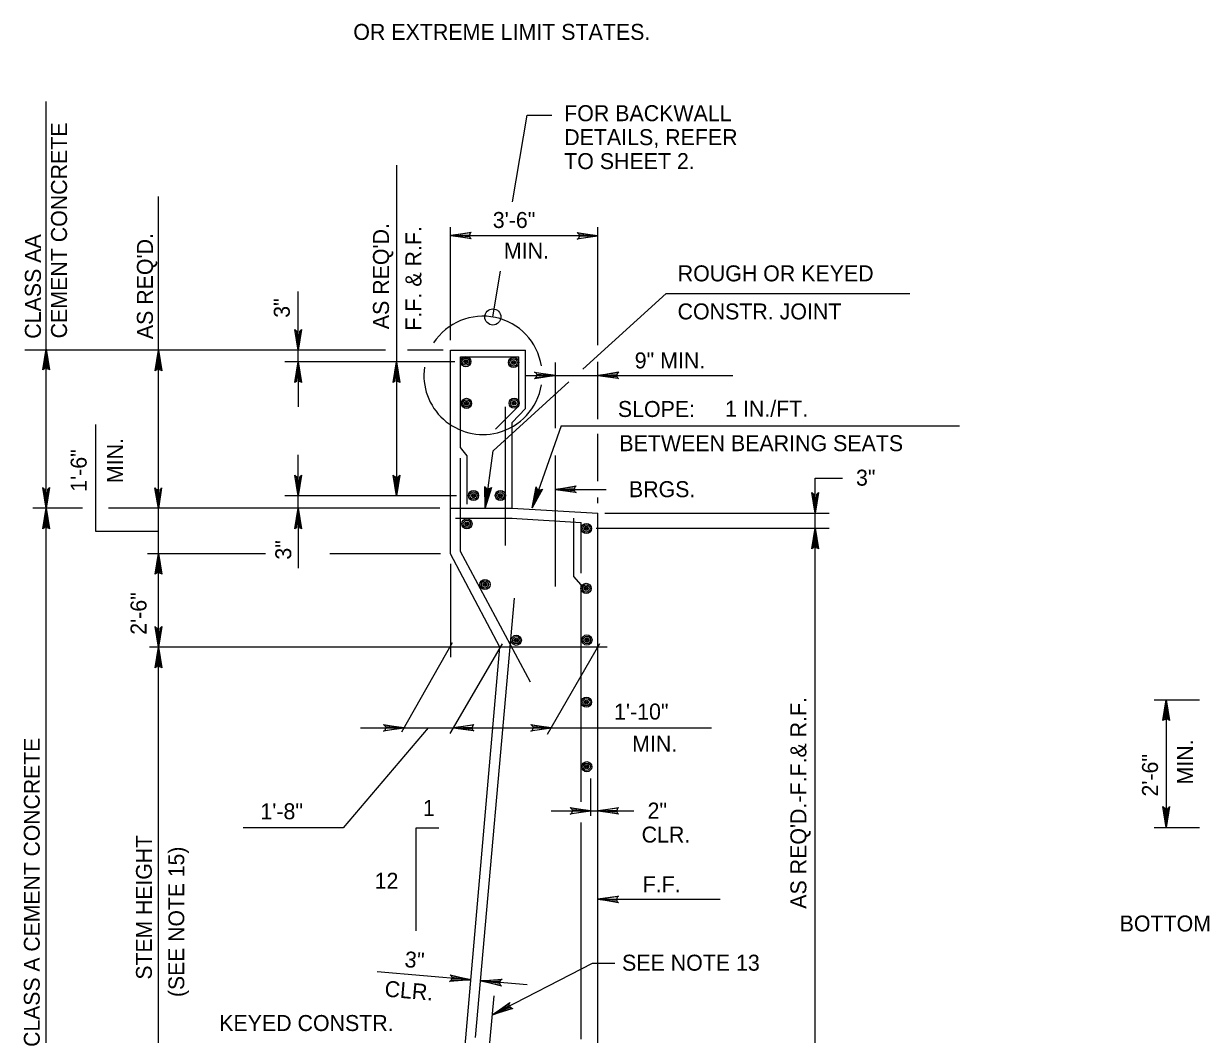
# Model space of a CAD drawing. Extents: x 235 to 2276, y 116 to 1308.
# Drawn here: x 855.9 to 1078.3, y 817.2 to 1006.9 of the extents above; entities that cross this region are included whole.
import ezdxf

# ---------------------------------------------------------------- set-up
doc = ezdxf.new("R2010")
doc.units = 0
doc.layers.add('1', color=7, linetype='Continuous')

msp = doc.modelspace()

# ---------------------------------------------------------------- linework, layer by layer
at = {"layer": '1'}
for p, q in [((860.12, 942.99), (860.12, 992.35)), ((947.67, 973.49), (950.43, 989.79)), ((950.43, 989.79), (955.07, 989.79)), ((925.92, 980.39), (925.92, 952.99)), ((881.22, 951.59), (881.22, 974.52)), ((936.06, 951.59), (936.06, 968.74)), ((963.72, 951.59), (963.72, 968.74)), ((936.06, 967.15), (963.72, 967.15)), ((944, 951.87), (945.46, 960.45)), ((907.47, 943.46), (907.47, 956.67)), ((960.91, 942.08), (976.53, 956.27)), ((976.53, 956.27), (1022.28, 956.27)), ((925.92, 952.99), (925.92, 941.43)), ((881.22, 945.65), (881.22, 951.59)), ((936.06, 947.52), (936.06, 951.59)), ((963.72, 946.59), (963.72, 951.59)), ((923.83, 945.65), (856.12, 945.65)), ((860.12, 915.96), (860.12, 945.65)), ((881.22, 915.96), (881.22, 945.65)), ((934.65, 945.65), (927.97, 945.65)), ((936.06, 907.37), (936.06, 945.65)), ((936.06, 945.65), (950.12, 945.65)), ((950.12, 934.71), (950.12, 945.65)), ((936.84, 943.46), (904.97, 943.46)), ((907.47, 943.46), (907.47, 935.02)), ((925.92, 943.46), (925.92, 918.3)), ((937.94, 944.4), (948.87, 944.4)), ((937.94, 927.37), (937.94, 944.4)), ((948.87, 935.18), (948.87, 944.4)), ((955.75, 930.99), (955.75, 943.34)), ((963.72, 941.43), (963.72, 943.46)), ((950.23, 940.91), (989.04, 940.91)), ((963.72, 932.65), (963.72, 941.43)), ((944.03, 926.74), (958.29, 939.7)), ((948.87, 935.18), (944.5, 930.8)), ((946.37, 908.93), (946.37, 935.02)), ((950.12, 934.71), (947.62, 932.05)), ((947.62, 915.96), (947.62, 932.05)), ((869.44, 911.59), (869.44, 931.69)), ((956.85, 931.43), (1031.62, 931.43)), ((963.72, 921.05), (963.72, 929.93)), ((907.47, 915.96), (907.47, 926.01)), ((939.19, 925.8), (937.94, 927.37)), ((937.94, 907.84), (937.94, 925.34)), ((939.19, 916.74), (939.19, 925.8)), ((942.62, 916.12), (944.03, 926.74)), ((955.75, 901.27), (955.75, 925.83)), ((1004.5, 912.21), (1004.5, 921.57)), ((1004.5, 921.57), (1009.63, 921.57)), ((955.75, 919.49), (965.28, 919.49)), ((937.15, 918.3), (904.97, 918.3)), ((963.72, 916.9), (963.72, 917.96)), ((866.93, 915.96), (857.62, 915.96)), ((860.12, 776.74), (860.12, 915.96)), ((934.03, 915.96), (871.82, 915.96)), ((881.22, 907.37), (881.22, 915.96)), ((907.47, 915.96), (907.47, 904.72)), ((936.06, 915.96), (947.62, 915.96)), ((947.62, 915.96), (963.72, 915.02)), ((963.72, 797.99), (963.72, 915.02)), ((965.01, 915.02), (1007.15, 915.02)), ((937, 914.09), (947.62, 914.09)), ((947.47, 914.09), (960.59, 913.3)), ((959.19, 903.15), (959.19, 914.09)), ((960.59, 903.77), (960.59, 913.3)), ((963.4, 912.21), (1007.15, 912.21)), ((1004.5, 800.65), (1004.5, 912.21)), ((881.22, 911.59), (869.44, 911.59)), ((951.06, 883.3), (937.94, 907.84)), ((901.29, 907.37), (879.17, 907.37)), ((881.22, 797.99), (881.22, 907.37)), ((934.19, 907.37), (913.4, 907.37)), ((945.28, 889.87), (936.06, 907.37)), ((936.06, 905.49), (936.06, 887.99)), ((960.59, 901.59), (959.19, 903.15)), ((960.59, 860.81), (960.59, 901.59)), ((940.75, 816.59), (948.09, 899.09)), ((965.44, 889.87), (879.5, 889.87)), ((936.37, 890.65), (926.84, 873.93)), ((945.75, 890.49), (935.9, 873.62)), ((937.31, 797.99), (945.28, 889.87)), ((964.03, 890.49), (954.19, 873.46)), ((1068.18, 879.97), (1076.68, 879.97)), ((1070.43, 879.97), (1070.43, 855.97)), ((931.84, 874.71), (915.9, 855.96)), ((919.12, 874.71), (936.53, 874.71)), ((936.53, 874.71), (954.97, 874.71)), ((954.97, 874.71), (985.06, 874.71)), ((962.39, 858.16), (962.39, 865.22)), ((954.97, 859.12), (962.39, 859.12)), ((962.39, 859.12), (963.72, 859.12)), ((963.72, 859.12), (970.49, 859.12)), ((960.59, 816.24), (960.59, 856.93)), ((915.9, 855.96), (897.12, 855.96)), ((929.61, 855.96), (933.83, 855.96)), ((929.61, 836.59), (929.61, 855.96)), ((1068.18, 855.97), (1076.68, 855.97)), ((963.72, 842.52), (986.69, 842.52)), ((962.66, 830.44), (943.9, 820.8)), ((966.9, 830.44), (962.66, 830.44)), ((939.65, 827.37), (922.25, 828.9)), ((950.44, 826.43), (941.69, 827.21)), ((941.1, 789.33), (944.23, 824.4))]:
    msp.add_line(p, q, dxfattribs=at)
for points in [[(939.78, 966.65), (939.66, 966.9), (936.03, 967.15), (939.78, 966.65), (939.91, 966.53), (936.03, 967.15), (939.66, 967.28), (939.78, 967.65), (936.03, 967.15), (939.91, 967.78), (939.78, 967.65)], [(959.94, 967.63), (960.19, 967.38), (963.69, 967.13), (959.94, 967.63), (959.81, 967.75), (963.69, 967.13), (960.19, 967), (960.06, 966.63), (963.69, 967.13), (959.81, 966.5), (960.06, 966.63)], [(907.97, 949.4), (907.72, 949.15), (907.47, 945.65), (907.97, 949.4), (908.09, 949.52), (907.47, 945.65), (907.34, 949.15), (907.09, 949.27), (907.47, 945.65), (906.84, 949.52), (907.09, 949.27)], [(859.61, 942.09), (859.86, 942.22), (860.11, 945.84), (859.61, 942.09), (859.48, 941.97), (860.11, 945.84), (860.23, 942.22), (860.61, 942.09), (860.11, 945.84), (860.73, 941.97), (860.61, 942.09)], [(880.71, 941.9), (880.96, 942.03), (881.21, 945.65), (880.71, 941.9), (880.59, 941.78), (881.21, 945.65), (881.34, 942.03), (881.71, 941.9), (881.21, 945.65), (881.84, 941.78), (881.71, 941.9)], [(906.97, 939.71), (907.22, 939.84), (907.47, 943.46), (906.97, 939.71), (906.84, 939.59), (907.47, 943.46), (907.59, 939.84), (907.97, 939.71), (907.47, 943.46), (908.09, 939.59), (907.97, 939.71)], [(925.42, 939.71), (925.67, 939.84), (925.92, 943.46), (925.42, 939.71), (925.29, 939.59), (925.92, 943.46), (926.04, 939.84), (926.42, 939.71), (925.92, 943.46), (926.54, 939.59), (926.42, 939.71)], [(952.09, 941.4), (952.21, 941.15), (955.84, 940.9), (952.09, 941.4), (951.84, 941.52), (955.84, 940.9), (952.21, 940.77), (952.09, 940.52), (955.84, 940.9), (951.84, 940.27), (952.09, 940.52)], [(967.47, 940.41), (967.34, 940.66), (963.72, 940.91), (967.47, 940.41), (967.59, 940.29), (963.72, 940.91), (967.34, 941.04), (967.47, 941.41), (963.72, 940.91), (967.59, 941.54), (967.47, 941.41)], [(956.85, 931.43), (951.37, 915.96)], [(907.97, 922.05), (907.72, 921.8), (907.47, 918.3), (907.97, 922.05), (908.09, 922.18), (907.47, 918.3), (907.34, 921.8), (907.09, 921.93), (907.47, 918.3), (906.84, 922.18), (907.09, 921.93)], [(926.42, 922.05), (926.17, 921.8), (925.92, 918.3), (926.42, 922.05), (926.54, 922.18), (925.92, 918.3), (925.79, 921.8), (925.54, 921.93), (925.92, 918.3), (925.29, 922.18), (925.54, 921.93)], [(860.62, 919.72), (860.37, 919.47), (860.12, 915.97), (860.62, 919.72), (860.75, 919.84), (860.12, 915.97), (860, 919.47), (859.62, 919.59), (860.12, 915.97), (859.5, 919.84), (859.62, 919.59)], [(881.69, 919.65), (881.44, 919.4), (881.19, 915.9), (881.69, 919.65), (881.81, 919.77), (881.19, 915.9), (881.06, 919.4), (880.69, 919.52), (881.19, 915.9), (880.56, 919.77), (880.69, 919.52)], [(943.53, 919.7), (943.24, 919.6), (942.56, 916.02), (943.53, 919.7), (943.72, 919.87), (942.56, 916.02), (942.86, 919.64), (942.61, 919.81), (942.56, 916.02), (942.46, 920.04), (942.61, 919.81)], [(953.09, 919.41), (952.78, 919.37), (951.38, 916.01), (953.09, 919.41), (953.31, 919.54), (951.38, 916.01), (952.42, 919.5), (952.21, 919.71), (951.38, 916.01), (952.11, 919.96), (952.21, 919.71)], [(959.48, 919), (959.36, 919.25), (955.73, 919.5), (959.48, 919), (959.61, 918.88), (955.73, 919.5), (959.36, 919.63), (959.48, 920), (955.73, 919.5), (959.61, 920.13), (959.48, 920)], [(1005, 918.77), (1004.75, 918.52), (1004.5, 915.02), (1005, 918.77), (1005.12, 918.9), (1004.5, 915.02), (1004.37, 918.52), (1004.12, 918.65), (1004.5, 915.02), (1003.87, 918.9), (1004.12, 918.65)], [(859.62, 912.23), (859.87, 912.35), (860.12, 915.98), (859.62, 912.23), (859.5, 912.1), (860.12, 915.98), (860.25, 912.35), (860.62, 912.23), (860.12, 915.98), (860.75, 912.1), (860.62, 912.23)], [(906.97, 912.21), (907.22, 912.34), (907.47, 915.96), (906.97, 912.21), (906.84, 912.09), (907.47, 915.96), (907.59, 912.34), (907.97, 912.21), (907.47, 915.96), (908.09, 912.09), (907.97, 912.21)], [(1004.04, 908.46), (1004.29, 908.59), (1004.54, 912.21), (1004.04, 908.46), (1003.91, 908.34), (1004.54, 912.21), (1004.66, 908.59), (1005.04, 908.46), (1004.54, 912.21), (1005.16, 908.34), (1005.04, 908.46)], [(880.73, 903.7), (880.98, 903.82), (881.23, 907.45), (880.73, 903.7), (880.61, 903.57), (881.23, 907.45), (881.36, 903.82), (881.73, 903.7), (881.23, 907.45), (881.86, 903.57), (881.73, 903.7)], [(881.7, 893.62), (881.45, 893.37), (881.2, 889.87), (881.7, 893.62), (881.83, 893.75), (881.2, 889.87), (881.08, 893.37), (880.7, 893.5), (881.2, 889.87), (880.58, 893.75), (880.7, 893.5)], [(880.72, 886.12), (880.97, 886.24), (881.22, 889.87), (880.72, 886.12), (880.59, 885.99), (881.22, 889.87), (881.34, 886.24), (881.72, 886.12), (881.22, 889.87), (881.84, 885.99), (881.72, 886.12)], [(1069.93, 876.22), (1070.3, 876.34), (1070.43, 879.97), (1069.93, 876.22), (1069.8, 876.09), (1070.43, 879.97), (1070.68, 876.34), (1070.93, 876.22), (1070.43, 879.97), (1071.05, 876.09), (1070.93, 876.22)], [(923.56, 875.21), (923.81, 874.96), (927.31, 874.71), (923.56, 875.21), (923.44, 875.34), (927.31, 874.71), (923.81, 874.59), (923.69, 874.21), (927.31, 874.71), (923.44, 874.09), (923.69, 874.21)], [(940.28, 874.24), (940.15, 874.49), (936.53, 874.74), (940.28, 874.24), (940.4, 874.12), (936.53, 874.74), (940.15, 874.87), (940.28, 875.24), (936.53, 874.74), (940.4, 875.37), (940.28, 875.24)], [(951.23, 875.21), (951.48, 874.96), (954.98, 874.71), (951.23, 875.21), (951.11, 875.34), (954.98, 874.71), (951.48, 874.59), (951.36, 874.21), (954.98, 874.71), (951.11, 874.09), (951.36, 874.21)], [(958.64, 859.62), (958.89, 859.37), (962.39, 859.12), (958.64, 859.62), (958.52, 859.75), (962.39, 859.12), (958.89, 859), (958.77, 858.62), (962.39, 859.12), (958.52, 858.5), (958.77, 858.62)], [(967.47, 858.62), (967.34, 858.87), (963.72, 859.12), (967.47, 858.62), (967.59, 858.5), (963.72, 859.12), (967.34, 859.25), (967.47, 859.62), (963.72, 859.12), (967.59, 859.75), (967.47, 859.62)], [(1070.93, 859.72), (1070.68, 859.59), (1070.43, 855.97), (1070.93, 859.72), (1071.05, 859.97), (1070.43, 855.97), (1070.3, 859.59), (1070.05, 859.72), (1070.43, 855.97), (1069.8, 859.97), (1070.05, 859.72)], [(967.43, 842.01), (967.31, 842.26), (963.68, 842.51), (967.43, 842.01), (967.56, 841.88), (963.68, 842.51), (967.31, 842.63), (967.43, 843.01), (963.68, 842.51), (967.56, 843.13), (967.43, 843.01)], [(936.17, 828.17), (936.29, 827.89), (939.9, 827.37), (936.17, 828.17), (935.99, 828.35), (939.9, 827.37), (936.26, 827.51), (936.1, 827.25), (939.9, 827.37), (935.88, 827.09), (936.1, 827.25)], [(945.44, 826.41), (945.32, 826.69), (941.72, 827.22), (945.44, 826.41), (945.62, 826.22), (941.72, 827.22), (945.35, 827.07), (945.51, 827.33), (941.72, 827.22), (945.73, 827.49), (945.51, 827.33)], [(947.49, 822.08), (947.24, 822.27), (943.9, 820.8), (947.49, 822.08), (947.74, 822.02), (943.9, 820.8), (947.07, 822.6), (947.06, 822.91), (943.9, 820.8), (947.17, 823.16), (947.06, 822.91)]]:
    msp.add_lwpolyline(points, dxfattribs=at)
for centre, radius in [((944, 951.87), 1.51), ((938.93, 943.48), 0.954), ((938.93, 943.48), 0.681), ((938.93, 943.48), 0.372), ((938.93, 943.48), 0.188), ((938.93, 943.48), 0.0805), ((947.89, 943.32), 0.954), ((947.89, 943.32), 0.681), ((947.89, 943.32), 0.372), ((947.89, 943.32), 0.188), ((947.89, 943.32), 0.0805), ((939.04, 935.65), 0.954), ((947.99, 935.69), 0.954), ((939.04, 935.65), 0.681), ((939.04, 935.65), 0.372), ((939.04, 935.65), 0.188), ((939.04, 935.65), 0.0805), ((947.99, 935.69), 0.681), ((947.99, 935.69), 0.372), ((947.99, 935.69), 0.188), ((947.99, 935.69), 0.0805), ((940.37, 918.33), 0.954), ((940.37, 918.33), 0.681), ((940.37, 918.33), 0.372), ((945.41, 918.33), 0.954), ((945.41, 918.33), 0.681), ((945.41, 918.33), 0.372), ((940.37, 918.33), 0.188), ((940.37, 918.33), 0.0805), ((945.41, 918.33), 0.188), ((945.41, 918.33), 0.0805), ((939.13, 913.01), 0.954), ((939.13, 913.01), 0.681), ((939.13, 913.01), 0.372), ((939.13, 913.01), 0.188), ((939.13, 913.01), 0.0805), ((961.56, 912.15), 0.954), ((961.56, 912.15), 0.681), ((961.56, 912.15), 0.372), ((961.56, 912.15), 0.188), ((961.56, 912.15), 0.0805), ((942.52, 901.64), 0.954), ((942.52, 901.64), 0.681), ((942.52, 901.64), 0.372), ((942.52, 901.64), 0.188), ((942.52, 901.64), 0.0805), ((961.5, 900.9), 0.954), ((961.5, 900.9), 0.681), ((961.5, 900.9), 0.372), ((961.5, 900.9), 0.188), ((961.5, 900.9), 0.0805), ((948.4, 891.16), 0.954), ((961.66, 891.21), 0.954), ((948.4, 891.16), 0.681), ((948.4, 891.16), 0.372), ((948.4, 891.16), 0.188), ((948.4, 891.16), 0.0805), ((961.66, 891.21), 0.681), ((961.66, 891.21), 0.372), ((961.66, 891.21), 0.188), ((961.66, 891.21), 0.0805), ((961.56, 879.53), 0.954), ((961.56, 879.53), 0.681), ((961.56, 879.53), 0.372), ((961.56, 879.53), 0.188), ((961.56, 879.53), 0.0805), ((961.62, 867.41), 0.954), ((961.62, 867.41), 0.681), ((961.62, 867.41), 0.372), ((961.62, 867.41), 0.188), ((961.62, 867.41), 0.0805)]:
    msp.add_circle(centre, radius, dxfattribs=at)
for start, end in [(9.2933, 146.6735), (172.0304, 284.0362), (284.0362, 350.7067)]:
    msp.add_arc((942.15, 940.91), 11.11, start, end, dxfattribs=at)

# ---------------------------------------------------------------- texts
for s, height, p in [('    OR EXTREME LIMIT STATES.', 3.003, (913.33, 1003.9)), ('FOR BACKWALL', 3, (957.39, 988.64)), ('DETAILS, REFER', 3, (957.39, 984.14)), ('TO SHEET 2.', 3, (957.39, 979.64)), ('3\'-6"', 3.003, (943.98, 968.58)), ('MIN.', 3, (946.07, 962.85)), ('ROUGH OR KEYED', 3, (978.71, 958.56)), ('CONSTR. JOINT', 3, (978.68, 951.41)), ('9" MIN.', 3.003, (970.63, 942.21)), ('SLOPE:', 3, (967.47, 933.09)), ('1 IN./FT.', 3.003, (987.6, 933.15)), ('BETWEEN BEARING SEATS', 3, (967.75, 926.67)), ('3"', 3.003, (1012.18, 920.19)), ('  BRGS.', 3, (967.31, 918.03)), ('1\'-10"', 3.003, (966.75, 876.26)), ('MIN.', 3, (970.14, 870.23)), ('1 ', 3, (930.86, 858.17)), ('1\'-8"', 3.003, (900.35, 857.54)), (' 2"', 3, (971.93, 857.67)), ('CLR.', 3, (971.93, 853.17)), ('12', 3, (921.8, 844.49)), ('F.F.', 3, (972.13, 843.83)), ('BOTTOM REBAR MAT (TYP.)', 3, (1061.68, 836.47)), ('SEE NOTE 13', 3, (968.25, 829.11)), ('KEYED CONSTR.', 3, (892.61, 817.78))]:
    msp.add_text(s, height=height, dxfattribs=at).set_placement(p)
for s, height, rotation, p in [('CEMENT CONCRETE', 3, 90, (864.04, 947.85)), ("AS REQ'D.", 3, 90, (924.49, 949.57)), ('F.F. & R.F.', 3, 90, (930.58, 949.31)), ('CLASS AA', 3, 90, (859.14, 947.78)), ("AS REQ'D.", 3, 90, (880.17, 947.7)), ('3"', 3, 90, (905.87, 951.72)), ('MIN.', 3, 90, (874.56, 920.67)), ('1\'-6"', 3, 90, (867.73, 919.04)), ('3"', 3, 90, (906.15, 906.3)), ('2\'-6"', 3, 90, (878.97, 892.19)), ("AS REQ'D.-F.F.& R.F.", 3, 90, (1002.86, 840.74)), ('CLASS A CEMENT CONCRETE', 2.97, 90, (858.92, 814.81)), ('MIN.', 3, 90, (1075.48, 864.07)), ('2\'-6"', 3, 90, (1068.88, 861.81)), ('STEM HEIGHT', 2.97, 90, (879.97, 827.44)), ('(SEE NOTE 15)', 2.97, 90, (886.05, 824.16)), ('3"', 3, 354.9865, (927.35, 829.79)), ('CLR.', 3, 354.9865, (923.58, 824.27))]:
    msp.add_text(s, height=height, rotation=rotation, dxfattribs=at).set_placement(p)

doc.saveas('drawing.dxf')
